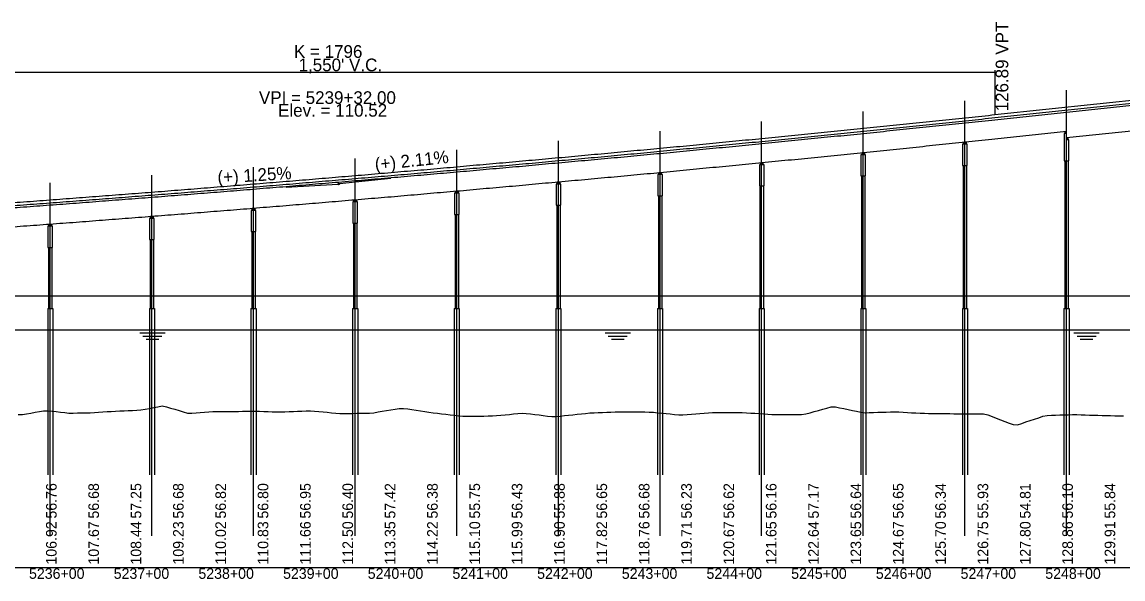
# Model space of a CAD drawing. Extents: x 2121671 to 2169879, y 557274 to 599957.
# Drawn here: x 2153126 to 2154426, y 579173 to 579831 of the extents above; entities that cross this region are included whole.
import ezdxf

# ---------------------------------------------------------------- set-up
doc = ezdxf.new("R2010")
doc.units = 0
for name, color, linetype in [('BR_CENTER LINES', 7, 'Continuous'), ('BR_CONCRETE', 7, 'Continuous'), ('BR_DETAILS', 7, 'Continuous'), ('BR_PRESTRESSED BEAM', 7, 'Continuous'), ('RD_DDB_GradeTX', 7, 'Continuous'), ('RD_DDB_Profile_Elev', 7, 'Continuous'), ('RD_DDB_Profile_EX', 7, 'Continuous'), ('RD_DDB_Profile_Lbl', 7, 'Continuous'), ('RD_DDB_Profile_PR', 7, 'Continuous'), ('RD_DDB_StaTX', 7, 'Continuous'), ('RD_DDB_StripGrade', 7, 'Continuous'), ('RD_DDB_VCLbl', 7, 'Continuous'), ('RD_GPK_Profile_Cell', 7, 'Continuous')]:
    doc.layers.add(name, color=color, linetype=linetype)

msp = doc.modelspace()

# ---------------------------------------------------------------- linework, layer by layer
at = {"layer": 'BR_CENTER LINES'}
for p, q in [((2154359.4, 579224.3), (2154359.4, 579750.2)), ((2154239.4, 579224.3), (2154239.4, 579737.6)), ((2154119.4, 579224.3), (2154119.4, 579725.2)), ((2153999.4, 579224.3), (2153999.4, 579713.3)), ((2153879.4, 579224.3), (2153879.4, 579701.7)), ((2153759.4, 579224.3), (2153759.4, 579690.5)), ((2153639.4, 579224.3), (2153639.4, 579679.8)), ((2153399.4, 579224.3), (2153399.4, 579659.5)), ((2153519.4, 579224.3), (2153519.4, 579669.4)), ((2153279.4, 579224.3), (2153279.4, 579649.9)), ((2153159.4, 579224.3), (2153159.4, 579640.8))]:
    msp.add_line(p, q, dxfattribs=at)
at = {"layer": 'BR_CONCRETE'}
for p, q in [((2154274.9, 579717.8), (2154567.9, 579748.7)), ((2154359.4, 579699), (2154356.7, 579699)), ((2154356.7, 579699), (2154356.7, 579666.7)), ((2154359.4, 579691.7), (2154359.4, 579699)), ((2154362.2, 579691.7), (2154359.4, 579691.7)), ((2154362.2, 579666.7), (2154362.2, 579691.7)), ((2154237.4, 579661.4), (2154237.4, 579492.4)), ((2154241.4, 579661.4), (2154241.4, 579492.4)), ((2154356.7, 579666.7), (2154362.2, 579666.7)), ((2154357.4, 579666.7), (2154357.4, 579492.4)), ((2154361.4, 579666.7), (2154361.4, 579492.4)), ((2154117.4, 579649), (2154117.4, 579492.4)), ((2154121.4, 579649), (2154121.4, 579492.4)), ((2153997.4, 579637.1), (2153997.4, 579492.4)), ((2154001.4, 579637.1), (2154001.4, 579492.4)), ((2153877.4, 579625.5), (2153877.4, 579492.4)), ((2153881.4, 579625.5), (2153881.4, 579492.4)), ((2153757.4, 579614.4), (2153757.4, 579492.4)), ((2153761.4, 579614.4), (2153761.4, 579492.4)), ((2153517.4, 579593.3), (2153517.4, 579492.4)), ((2153521.4, 579593.3), (2153521.4, 579492.4)), ((2153637.4, 579603.6), (2153637.4, 579492.4)), ((2153641.4, 579603.6), (2153641.4, 579492.4)), ((2153397.4, 579583.3), (2153397.4, 579492.4)), ((2153401.4, 579583.3), (2153401.4, 579492.4)), ((2153277.4, 579573.8), (2153277.4, 579492.4)), ((2153281.4, 579573.8), (2153281.4, 579492.4)), ((2153157.4, 579564.6), (2153157.4, 579492.4)), ((2153161.4, 579564.6), (2153161.4, 579492.4)), ((2153156.4, 579492.4), (2153156.4, 579296.1)), ((2153156.4, 579492.4), (2153162.4, 579492.4)), ((2153162.4, 579492.4), (2153162.4, 579296.1)), ((2153276.4, 579492.4), (2153276.4, 579296.1)), ((2153276.4, 579492.4), (2153282.4, 579492.4)), ((2153282.4, 579492.4), (2153282.4, 579296.1)), ((2153396.4, 579492.4), (2153396.4, 579296.1)), ((2153396.4, 579492.4), (2153402.4, 579492.4)), ((2153402.4, 579492.4), (2153402.4, 579296.1)), ((2153516.4, 579492.4), (2153516.4, 579296.1)), ((2153516.4, 579492.4), (2153522.4, 579492.4)), ((2153522.4, 579492.4), (2153522.4, 579296.1)), ((2153636.4, 579492.4), (2153636.4, 579296.1)), ((2153636.4, 579492.4), (2153642.4, 579492.4)), ((2153642.4, 579492.4), (2153642.4, 579296.1)), ((2153756.4, 579492.4), (2153756.4, 579296.1)), ((2153756.4, 579492.4), (2153762.4, 579492.4)), ((2153762.4, 579492.4), (2153762.4, 579296.1)), ((2153876.4, 579492.4), (2153876.4, 579296.1)), ((2153876.4, 579492.4), (2153882.4, 579492.4)), ((2153882.4, 579492.4), (2153882.4, 579296.1)), ((2153996.4, 579492.4), (2153996.4, 579296.1)), ((2153996.4, 579492.4), (2154002.4, 579492.4)), ((2154002.4, 579492.4), (2154002.4, 579296.1)), ((2154116.4, 579492.4), (2154116.4, 579296.1)), ((2154116.4, 579492.4), (2154122.4, 579492.4)), ((2154122.4, 579492.4), (2154122.4, 579296.1)), ((2154236.4, 579492.4), (2154236.4, 579296.1)), ((2154236.4, 579492.4), (2154242.4, 579492.4)), ((2154242.4, 579492.4), (2154242.4, 579296.1)), ((2154356.4, 579492.4), (2154356.4, 579296.1)), ((2154356.4, 579492.4), (2154362.4, 579492.4)), ((2154362.4, 579492.4), (2154362.4, 579296.1))]:
    msp.add_line(p, q, dxfattribs=at)
for points in [[(2154236.7, 579661.4), (2154242.2, 579661.4), (2154242.2, 579686.4), (2154236.7, 579686.4)], [(2154116.7, 579649), (2154122.2, 579649), (2154122.2, 579674), (2154116.7, 579674)], [(2153996.7, 579637.1), (2154002.2, 579637.1), (2154002.2, 579662.1), (2153996.7, 579662.1)], [(2153876.7, 579625.5), (2153882.2, 579625.5), (2153882.2, 579650.5), (2153876.7, 579650.5)], [(2153756.7, 579614.4), (2153762.2, 579614.4), (2153762.2, 579639.4), (2153756.7, 579639.4)], [(2153516.7, 579593.3), (2153522.2, 579593.3), (2153522.2, 579618.3), (2153516.7, 579618.3)], [(2153636.7, 579603.6), (2153642.2, 579603.6), (2153642.2, 579628.6), (2153636.7, 579628.6)], [(2153396.7, 579583.3), (2153402.2, 579583.3), (2153402.2, 579608.3), (2153396.7, 579608.3)], [(2153276.7, 579573.8), (2153282.2, 579573.8), (2153282.2, 579598.8), (2153276.7, 579598.8)], [(2153156.7, 579564.6), (2153162.2, 579564.6), (2153162.2, 579589.6), (2153156.7, 579589.6)]]:
    msp.add_lwpolyline(points, close=True, dxfattribs=at)
msp.add_spline([(2152724.9, 579587.5), (2152755.9, 579589.4), (2152786.9, 579591.4), (2152817.9, 579593.4), (2152848.9, 579595.4), (2152879.9, 579597.5), (2152910.9, 579599.6), (2152941.9, 579601.7), (2152972.9, 579603.8), (2153003.9, 579606), (2153034.9, 579608.2), (2153065.9, 579610.4), (2153096.9, 579612.6), (2153127.9, 579614.9), (2153158.9, 579617.2), (2153189.9, 579619.5), (2153220.9, 579621.9), (2153251.9, 579624.3), (2153282.9, 579626.7), (2153313.9, 579629.1), (2153344.9, 579631.6), (2153375.9, 579634), (2153406.9, 579636.6), (2153437.9, 579639.1), (2153468.9, 579641.7), (2153499.9, 579644.3), (2153530.9, 579646.9), (2153561.9, 579649.5), (2153592.9, 579652.2), (2153623.9, 579654.9), (2153654.9, 579657.6), (2153685.9, 579660.4), (2153716.9, 579663.1), (2153747.9, 579666), (2153778.9, 579668.8), (2153809.9, 579671.6), (2153840.9, 579674.5), (2153871.9, 579677.4), (2153902.9, 579680.4), (2153933.9, 579683.4), (2153964.9, 579686.3), (2153995.9, 579689.4), (2154026.9, 579692.4), (2154057.9, 579695.5), (2154088.9, 579698.6), (2154119.9, 579701.7), (2154150.9, 579704.9), (2154181.9, 579708.1), (2154212.9, 579711.3), (2154243.9, 579714.5), (2154274.9, 579717.8)], degree=3, dxfattribs=at)
at = {"layer": 'BR_DETAILS'}
for points in [[(2154357.9, 579701.5), (2154358.9, 579701.5), (2154358.9, 579699), (2154357.9, 579699)], [(2154237.9, 579688.9), (2154238.9, 579688.9), (2154238.9, 579686.4), (2154237.9, 579686.4)], [(2154239.9, 579688.9), (2154240.9, 579688.9), (2154240.9, 579686.4), (2154239.9, 579686.4)], [(2154359.9, 579694.2), (2154360.9, 579694.2), (2154360.9, 579691.7), (2154359.9, 579691.7)], [(2154117.9, 579676.5), (2154118.9, 579676.5), (2154118.9, 579674), (2154117.9, 579674)], [(2154119.9, 579676.5), (2154120.9, 579676.5), (2154120.9, 579674), (2154119.9, 579674)], [(2153997.9, 579664.6), (2153998.9, 579664.6), (2153998.9, 579662.1), (2153997.9, 579662.1)], [(2153999.9, 579664.6), (2154000.9, 579664.6), (2154000.9, 579662.1), (2153999.9, 579662.1)], [(2153877.9, 579653), (2153878.9, 579653), (2153878.9, 579650.5), (2153877.9, 579650.5)], [(2153879.9, 579653), (2153880.9, 579653), (2153880.9, 579650.5), (2153879.9, 579650.5)], [(2153637.9, 579631.1), (2153638.9, 579631.1), (2153638.9, 579628.6), (2153637.9, 579628.6)], [(2153639.9, 579631.1), (2153640.9, 579631.1), (2153640.9, 579628.6), (2153639.9, 579628.6)], [(2153757.9, 579641.9), (2153758.9, 579641.9), (2153758.9, 579639.4), (2153757.9, 579639.4)], [(2153759.9, 579641.9), (2153760.9, 579641.9), (2153760.9, 579639.4), (2153759.9, 579639.4)], [(2153517.9, 579620.8), (2153518.9, 579620.8), (2153518.9, 579618.3), (2153517.9, 579618.3)], [(2153519.9, 579620.8), (2153520.9, 579620.8), (2153520.9, 579618.3), (2153519.9, 579618.3)], [(2153397.9, 579610.8), (2153398.9, 579610.8), (2153398.9, 579608.3), (2153397.9, 579608.3)], [(2153399.9, 579610.8), (2153400.9, 579610.8), (2153400.9, 579608.3), (2153399.9, 579608.3)], [(2153157.9, 579592.1), (2153158.9, 579592.1), (2153158.9, 579589.6), (2153157.9, 579589.6)], [(2153159.9, 579592.1), (2153160.9, 579592.1), (2153160.9, 579589.6), (2153159.9, 579589.6)], [(2153277.9, 579601.3), (2153278.9, 579601.3), (2153278.9, 579598.8), (2153277.9, 579598.8)], [(2153279.9, 579601.3), (2153280.9, 579601.3), (2153280.9, 579598.8), (2153279.9, 579598.8)]]:
    msp.add_lwpolyline(points, close=True, dxfattribs=at)
at = {"layer": 'BR_PRESTRESSED BEAM'}
for p, q in [((2154274.9, 579715.3), (2154567.9, 579746.2)), ((2154359.4, 579694.2), (2154567.9, 579716.2)), ((2154274.9, 579692.8), (2154359.4, 579701.7))]:
    msp.add_line(p, q, dxfattribs=at)
for points in [[(2152724.9, 579585), (2152755.9, 579586.9), (2152786.9, 579588.9), (2152817.9, 579590.9), (2152848.9, 579592.9), (2152879.9, 579595), (2152910.9, 579597.1), (2152941.9, 579599.2), (2152972.9, 579601.3), (2153003.9, 579603.5), (2153034.9, 579605.7), (2153065.9, 579607.9), (2153096.9, 579610.1), (2153127.9, 579612.4), (2153158.9, 579614.7), (2153189.9, 579617), (2153220.9, 579619.4), (2153251.9, 579621.8), (2153282.9, 579624.2), (2153313.9, 579626.6), (2153344.9, 579629.1), (2153375.9, 579631.5), (2153406.9, 579634.1), (2153437.9, 579636.6), (2153468.9, 579639.2), (2153499.9, 579641.8), (2153530.9, 579644.4), (2153561.9, 579647), (2153592.9, 579649.7), (2153623.9, 579652.4), (2153654.9, 579655.1), (2153685.9, 579657.9), (2153716.9, 579660.6), (2153747.9, 579663.5), (2153778.9, 579666.3), (2153809.9, 579669.1), (2153840.9, 579672), (2153871.9, 579674.9), (2153902.9, 579677.9), (2153933.9, 579680.9), (2153964.9, 579683.8), (2153995.9, 579686.9), (2154026.9, 579689.9), (2154057.9, 579693), (2154088.9, 579696.1), (2154119.9, 579699.2), (2154150.9, 579702.4), (2154181.9, 579705.6), (2154212.9, 579708.8), (2154243.9, 579712), (2154274.9, 579715.3)], [(2152724.9, 579562.5), (2152755.9, 579564.4), (2152786.9, 579566.4), (2152817.9, 579568.4), (2152848.9, 579570.4), (2152879.9, 579572.5), (2152910.9, 579574.6), (2152941.9, 579576.7), (2152972.9, 579578.8), (2153003.9, 579581), (2153034.9, 579583.2), (2153065.9, 579585.4), (2153096.9, 579587.6), (2153127.9, 579589.9), (2153158.9, 579592.2), (2153189.9, 579594.5), (2153220.9, 579596.9), (2153251.9, 579599.3), (2153282.9, 579601.7), (2153313.9, 579604.1), (2153344.9, 579606.6), (2153375.9, 579609), (2153406.9, 579611.6), (2153437.9, 579614.1), (2153468.9, 579616.7), (2153499.9, 579619.3), (2153530.9, 579621.9), (2153561.9, 579624.5), (2153592.9, 579627.2), (2153623.9, 579629.9), (2153654.9, 579632.6), (2153685.9, 579635.4), (2153716.9, 579638.1), (2153747.9, 579641), (2153778.9, 579643.8), (2153809.9, 579646.6), (2153840.9, 579649.5), (2153871.9, 579652.4), (2153902.9, 579655.4), (2153933.9, 579658.4), (2153964.9, 579661.3), (2153995.9, 579664.4), (2154026.9, 579667.4), (2154057.9, 579670.5), (2154088.9, 579673.6), (2154119.9, 579676.7), (2154150.9, 579679.9), (2154181.9, 579683.1), (2154212.9, 579686.3), (2154243.9, 579689.5), (2154274.9, 579692.8)]]:
    msp.add_spline(points, degree=3, dxfattribs=at)
at = {"layer": 'RD_DDB_GradeTX'}
for p, q in [((2153561.6, 579645.9), (2153500.9, 579639.5)), ((2153438.1, 579635.6), (2153498.9, 579639.4))]:
    msp.add_line(p, q, dxfattribs=at)
msp.add_circle((2153499.9, 579639.4), 1, dxfattribs=at)
at = {"layer": 'RD_DDB_Profile_Elev'}
for p, q in [((2151922.4, 579507.4), (2155499.4, 579507.4)), ((2151953.5, 579467.4), (2156316.6, 579467.4)), ((2153265, 579463.7), (2153295, 579463.7)), ((2153814.5, 579463.7), (2153844.5, 579463.7)), ((2154368.1, 579463.7), (2154398.1, 579463.7)), ((2153268.8, 579459.9), (2153291.3, 579459.9)), ((2153272.5, 579456.2), (2153287.5, 579456.2)), ((2153818.2, 579459.9), (2153840.7, 579459.9)), ((2153822, 579456.2), (2153837, 579456.2)), ((2154371.8, 579459.9), (2154394.3, 579459.9)), ((2154375.6, 579456.2), (2154390.6, 579456.2))]:
    msp.add_line(p, q, dxfattribs=at)
at = {"layer": 'RD_DDB_Profile_EX'}
for points in [[(2153121.5, 579367.5), (2153126.5, 579367.4), (2153131.5, 579368.3), (2153136.5, 579369.2), (2153141.5, 579370.1), (2153146.5, 579371), (2153151.5, 579371.9), (2153156.5, 579371.9), (2153161.5, 579371.3), (2153166.5, 579370.8), (2153171.5, 579370.3), (2153176.5, 579369.7), (2153181.5, 579369.1), (2153186.5, 579369.2), (2153191.5, 579369.3), (2153196.5, 579369.4), (2153201.5, 579369.5), (2153206.5, 579369.6), (2153211.5, 579369.8), (2153216.5, 579370.1), (2153221.5, 579370.5)], [(2153221.5, 579370.5), (2153226.5, 579370.8), (2153231.5, 579371.1), (2153236.5, 579371.5), (2153241.5, 579371.7), (2153246.5, 579371.9), (2153251.5, 579372.1), (2153256.5, 579372.2), (2153261.5, 579372.4), (2153266.5, 579372.8), (2153271.5, 579373.7), (2153276.5, 579374.7), (2153281.5, 579375.6), (2153286.5, 579376.5), (2153291.5, 579377.5), (2153296.5, 579376.6), (2153301.5, 579375.1), (2153306.5, 579373.6), (2153311.5, 579372.1), (2153316.5, 579370.7), (2153321.5, 579369.2), (2153326.5, 579369.2), (2153331.5, 579369.5), (2153336.5, 579369.9), (2153341.5, 579370.2), (2153346.5, 579370.5), (2153351.5, 579370.8), (2153356.5, 579371.1), (2153361.5, 579370.9), (2153366.5, 579370.9), (2153371.5, 579371), (2153376.5, 579371), (2153381.5, 579371.1), (2153386.5, 579371.2), (2153391.5, 579371.2), (2153396.5, 579371.5), (2153401.5, 579371.3), (2153406.5, 579371.2), (2153411.5, 579371), (2153416.5, 579370.9), (2153421.5, 579370.7), (2153426.5, 579370.6), (2153431.5, 579370.4), (2153436.5, 579370.6), (2153441.5, 579370.8), (2153446.5, 579371), (2153451.5, 579371.2), (2153456.5, 579371.4), (2153461.5, 579371.6), (2153466.5, 579371.7), (2153471.5, 579371.3), (2153476.5, 579370.9), (2153481.5, 579370.4), (2153486.5, 579370), (2153491.5, 579369.5), (2153496.5, 579369.1), (2153501.5, 579368.6), (2153506.5, 579368.6), (2153511.5, 579368.7), (2153516.5, 579368.8), (2153521.5, 579368.9), (2153526.5, 579369), (2153531.5, 579369.1), (2153536.5, 579369.1), (2153541.5, 579369.5), (2153546.5, 579370.4), (2153551.5, 579371.2), (2153556.5, 579372), (2153561.5, 579372.9), (2153566.5, 579373.7), (2153571.5, 579374.5), (2153576.5, 579374.7), (2153581.5, 579374), (2153586.5, 579373.2), (2153591.5, 579372.4), (2153596.5, 579371.6), (2153601.5, 579370.9), (2153606.5, 579370.1), (2153611.5, 579369.5), (2153616.5, 579368.9), (2153621.5, 579368.3), (2153626.5, 579367.7), (2153631.5, 579367.1), (2153636.5, 579366.5), (2153641.5, 579365.9), (2153646.5, 579365.3), (2153651.5, 579365.4), (2153656.5, 579365.4), (2153661.5, 579365.5), (2153666.5, 579365.6), (2153671.5, 579365.6), (2153676.5, 579365.7), (2153681.5, 579365.8), (2153686.5, 579366.1), (2153691.5, 579366.6), (2153696.5, 579367.1), (2153701.5, 579367.6), (2153706.5, 579368.1), (2153711.5, 579368.6), (2153716.5, 579369.1), (2153721.5, 579368.8)], [(2153721.5, 579368.8), (2153726.5, 579368.1), (2153731.5, 579367.5), (2153736.5, 579366.9), (2153741.5, 579366.2), (2153746.5, 579365.6), (2153751.5, 579365), (2153756.5, 579365), (2153761.5, 579365.6), (2153766.5, 579366.1), (2153771.5, 579366.6), (2153776.5, 579367.2), (2153781.5, 579367.7), (2153786.5, 579368.2), (2153791.5, 579368.8), (2153796.5, 579369.3), (2153801.5, 579369.5), (2153806.5, 579369.7), (2153811.5, 579369.8), (2153816.5, 579370), (2153821.5, 579370.2), (2153826.5, 579370.4), (2153831.5, 579370.6), (2153836.5, 579370.6), (2153841.5, 579370.6), (2153846.5, 579370.5), (2153851.5, 579370.5), (2153856.5, 579370.4), (2153861.5, 579370.4), (2153866.5, 579370.3), (2153871.5, 579370), (2153876.5, 579369.5), (2153881.5, 579369), (2153886.5, 579368.5), (2153891.5, 579368.1), (2153896.5, 579367.6), (2153901.5, 579367.1), (2153906.5, 579367), (2153911.5, 579367.4), (2153916.5, 579367.8), (2153921.5, 579368.3), (2153926.5, 579368.7), (2153931.5, 579369.1), (2153936.5, 579369.5), (2153941.5, 579369.9), (2153946.5, 579369.9), (2153951.5, 579369.9), (2153956.5, 579369.9), (2153961.5, 579369.9), (2153966.5, 579369.9), (2153971.5, 579369.9), (2153976.5, 579369.9), (2153981.5, 579369.6), (2153986.5, 579369.2), (2153991.5, 579368.9), (2153996.5, 579368.6), (2154001.5, 579368.3), (2154006.5, 579367.9), (2154011.5, 579367.6), (2154016.5, 579367.6), (2154021.5, 579367.6), (2154026.5, 579367.6), (2154031.5, 579367.6), (2154036.5, 579367.6), (2154041.5, 579367.6), (2154046.5, 579367.5), (2154051.5, 579368.2), (2154056.5, 579369.6), (2154061.5, 579370.9), (2154066.5, 579372.3), (2154071.5, 579373.7), (2154076.5, 579375.1), (2154081.5, 579376.4), (2154086.5, 579376.6), (2154091.5, 579375.5), (2154096.5, 579374.5), (2154101.5, 579373.4), (2154106.5, 579372.3), (2154111.5, 579371.3), (2154116.5, 579370.2), (2154121.5, 579369.6), (2154126.5, 579369.7), (2154131.5, 579369.9), (2154136.5, 579370), (2154141.5, 579370.2), (2154146.5, 579370.3), (2154151.5, 579370.5), (2154156.5, 579370.6), (2154161.5, 579370.4), (2154166.5, 579370.1), (2154171.5, 579369.9), (2154176.5, 579369.6), (2154181.5, 579369.4), (2154186.5, 579369.1), (2154191.5, 579368.9), (2154196.5, 579368.8), (2154201.5, 579368.7), (2154206.5, 579368.7), (2154211.5, 579368.6), (2154216.5, 579368.5), (2154221.5, 579368.5)], [(2154221.5, 579368.5), (2154226.5, 579368.4), (2154231.5, 579368.4), (2154236.5, 579368.4), (2154241.5, 579368.3), (2154246.5, 579368.3), (2154251.5, 579368.2), (2154256.5, 579368.2), (2154261.5, 579368.2), (2154266.5, 579367), (2154271.5, 579365.1), (2154276.5, 579363.2), (2154281.5, 579361.3), (2154286.5, 579359.3), (2154291.5, 579357.4), (2154296.5, 579355.5), (2154301.5, 579355.3), (2154306.5, 579357), (2154311.5, 579358.7), (2154316.5, 579360.4), (2154321.5, 579362.1), (2154326.5, 579363.7), (2154331.5, 579365.4), (2154336.5, 579366.4), (2154341.5, 579366.6), (2154346.5, 579366.7), (2154351.5, 579366.9), (2154356.5, 579367), (2154361.5, 579367.2), (2154366.5, 579367.3), (2154371.5, 579367.3), (2154376.5, 579367.2), (2154381.5, 579367), (2154386.5, 579366.8), (2154391.5, 579366.7), (2154396.5, 579366.5), (2154401.5, 579366.3), (2154406.5, 579366.2), (2154411.5, 579366.1), (2154416.5, 579366), (2154421.5, 579366), (2154426.5, 579365.9)]]:
    msp.add_lwpolyline(points, dxfattribs=at)
at = {"layer": 'RD_DDB_Profile_PR'}
msp.add_line((2154274.9, 579721.3), (2154567.9, 579752.2), dxfattribs=at)
msp.add_spline([(2152724.9, 579591), (2152755.9, 579593), (2152786.9, 579594.9), (2152817.9, 579596.9), (2152848.9, 579599), (2152879.9, 579601), (2152910.9, 579603.1), (2152941.9, 579605.2), (2152972.9, 579607.4), (2153003.9, 579609.5), (2153034.9, 579611.7), (2153065.9, 579613.9), (2153096.9, 579616.2), (2153127.9, 579618.4), (2153158.9, 579620.7), (2153189.9, 579623.1), (2153220.9, 579625.4), (2153251.9, 579627.8), (2153282.9, 579630.2), (2153313.9, 579632.6), (2153344.9, 579635.1), (2153375.9, 579637.6), (2153406.9, 579640.1), (2153437.9, 579642.6), (2153468.9, 579645.2), (2153499.9, 579647.8), (2153530.9, 579650.4), (2153561.9, 579653.1), (2153592.9, 579655.7), (2153623.9, 579658.4), (2153654.9, 579661.2), (2153685.9, 579663.9), (2153716.9, 579666.7), (2153747.9, 579669.5), (2153778.9, 579672.3), (2153809.9, 579675.2), (2153840.9, 579678.1), (2153871.9, 579681), (2153902.9, 579683.9), (2153933.9, 579686.9), (2153964.9, 579689.9), (2153995.9, 579692.9), (2154026.9, 579696), (2154057.9, 579699), (2154088.9, 579702.1), (2154119.9, 579705.3), (2154150.9, 579708.4), (2154181.9, 579711.6), (2154212.9, 579714.8), (2154243.9, 579718), (2154274.9, 579721.3)], degree=3, dxfattribs=at)
at = {"layer": 'RD_DDB_VCLbl'}
for p, q in [((2152724.9, 579771.3), (2154274.9, 579771.3)), ((2154274.9, 579773.8), (2154274.9, 579721.3))]:
    msp.add_line(p, q, dxfattribs=at)
at = {"layer": 'RD_GPK_Profile_Cell'}
msp.add_line((2151067.9, 579186.8), (2157367.9, 579186.8), dxfattribs=at)

# ---------------------------------------------------------------- texts
at = {"layer": 'RD_DDB_GradeTX'}
for s, rotation, p in [('(+) 2.11%', 6.0299, (2153543.4, 579655.2)), ('(+) 1.25%', 3.5756, (2153357.3, 579639.8))]:
    msp.add_text(s, height=15, rotation=rotation, dxfattribs=at).set_placement(p)
at = {"layer": 'RD_DDB_Profile_Lbl'}
for s, p in [('VPI = 5239+32.00', (2153405.8, 579733.9)), ('Elev. = 110.52', (2153428.4, 579718.9))]:
    msp.add_text(s, height=15, dxfattribs=at).set_placement(p)
at = {"layer": 'RD_DDB_StaTX'}
for s, p in [('5236+00', (2153134.3, 579173.5)), ('5237+00', (2153234.3, 579173.5)), ('5238+00', (2153334.3, 579173.5)), ('5239+00', (2153434.3, 579173.5)), ('5240+00', (2153534.3, 579173.5)), ('5241+00', (2153634.3, 579173.5)), ('5242+00', (2153734.3, 579173.5)), ('5243+00', (2153834.3, 579173.5)), ('5244+00', (2153934.3, 579173.5)), ('5245+00', (2154034.3, 579173.5)), ('5246+00', (2154134.3, 579173.5)), ('5247+00', (2154234.3, 579173.5)), ('5248+00', (2154334.3, 579173.5))]:
    msp.add_text(s, height=12.5, dxfattribs=at).set_placement(p)
at = {"layer": 'RD_DDB_StripGrade'}
for s, height, p in [('126.89 VPT', 15, (2154290.7, 579725.1)), ('56.76', 12.5, (2153166.9, 579244.6)), ('56.68', 12.5, (2153216.9, 579244.6)), ('57.25', 12.5, (2153266.9, 579244.6)), ('56.68', 12.5, (2153316.9, 579244.6)), ('56.82', 12.5, (2153366.9, 579244.6)), ('56.80', 12.5, (2153416.9, 579244.6)), ('56.95', 12.5, (2153466.9, 579244.6)), ('56.40', 12.5, (2153516.9, 579244.6)), ('57.42', 12.5, (2153566.9, 579244.6)), ('56.38', 12.5, (2153616.9, 579244.6)), ('55.75', 12.5, (2153666.9, 579244.6)), ('56.43', 12.5, (2153716.9, 579244.6)), ('55.88', 12.5, (2153766.9, 579244.6)), ('56.65', 12.5, (2153816.9, 579244.6)), ('56.68', 12.5, (2153866.9, 579244.6)), ('56.23', 12.5, (2153916.9, 579244.6)), ('56.62', 12.5, (2153966.9, 579244.6)), ('56.16', 12.5, (2154016.9, 579244.6)), ('57.17', 12.5, (2154066.9, 579244.6)), ('56.64', 12.5, (2154116.9, 579244.6)), ('56.65', 12.5, (2154166.9, 579244.6)), ('56.34', 12.5, (2154216.9, 579244.6)), ('55.93', 12.5, (2154266.9, 579244.6)), ('54.81', 12.5, (2154316.9, 579244.6)), ('56.10', 12.5, (2154366.9, 579244.6)), ('55.84', 12.5, (2154416.9, 579244.6)), ('106.92', 12.5, (2153166.9, 579190.3)), ('107.67', 12.5, (2153216.9, 579190.3)), ('108.44', 12.5, (2153266.9, 579190.3)), ('109.23', 12.5, (2153316.9, 579190.3)), ('110.02', 12.5, (2153366.9, 579190.3)), ('110.83', 12.5, (2153416.9, 579190.3)), ('111.66', 12.5, (2153466.9, 579190.3)), ('112.50', 12.5, (2153516.9, 579190.3)), ('113.35', 12.5, (2153566.9, 579190.3)), ('114.22', 12.5, (2153616.9, 579190.3)), ('115.10', 12.5, (2153666.9, 579190.3)), ('115.99', 12.5, (2153716.9, 579190.3)), ('116.90', 12.5, (2153766.9, 579190.3)), ('117.82', 12.5, (2153816.9, 579190.3)), ('118.76', 12.5, (2153866.9, 579190.3)), ('119.71', 12.5, (2153916.9, 579190.3)), ('120.67', 12.5, (2153966.9, 579190.3)), ('121.65', 12.5, (2154016.9, 579190.3)), ('122.64', 12.5, (2154066.9, 579190.3)), ('123.65', 12.5, (2154116.9, 579190.3)), ('124.67', 12.5, (2154166.9, 579190.3)), ('125.70', 12.5, (2154216.9, 579190.3)), ('126.75', 12.5, (2154266.9, 579190.3)), ('127.80', 12.5, (2154316.9, 579190.3)), ('128.86', 12.5, (2154366.9, 579190.3)), ('129.91', 12.5, (2154416.9, 579190.3))]:
    msp.add_text(s, height=height, rotation=90, dxfattribs=at).set_placement(p)
at = {"layer": 'RD_DDB_VCLbl'}
for s, p in [('K = 1796', (2153447.1, 579788.3)), ("1,550' V.C.", (2153452.6, 579772.5))]:
    msp.add_text(s, height=15, dxfattribs=at).set_placement(p)

doc.saveas('drawing.dxf')
